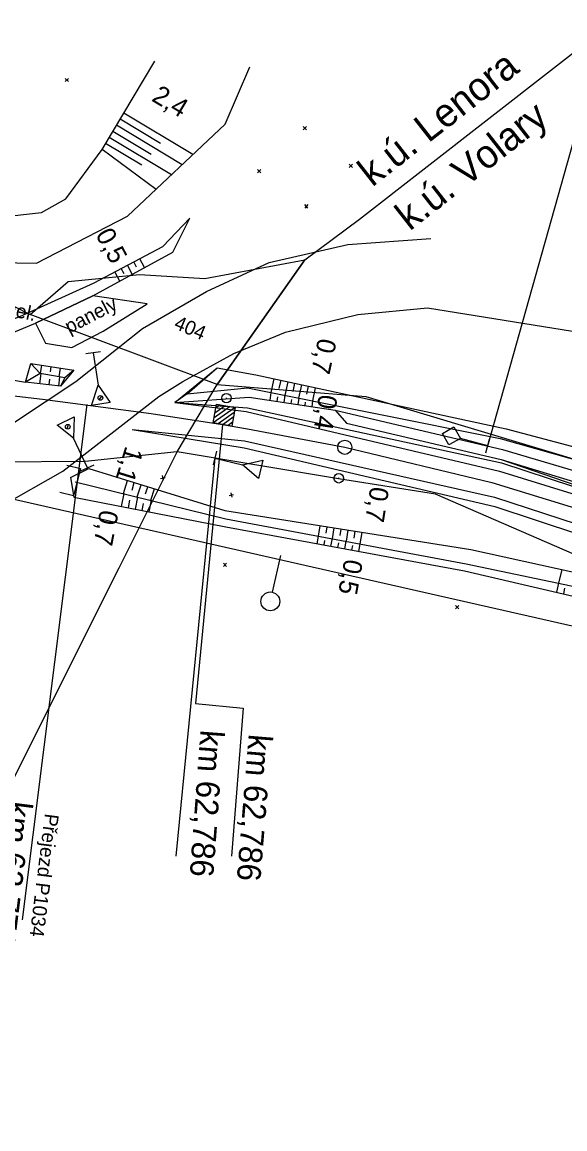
# Model space of a CAD drawing. Extents: x -804899 to -803847, y -1165742 to -1164942.
# Drawn here: x -804772 to -804714.3, y -1165193.1 to -1165075.5 of the extents above; entities that cross this region are included whole.
import ezdxf

# ---------------------------------------------------------------- set-up
doc = ezdxf.new("R2010")
doc.units = 0
for name, color, linetype in [('0381KM061-064P - Vrstva 1', 7, 'Continuous'), ('0381KM061-064P - Vrstva 16', 7, 'Continuous'), ('0381KM061-064P - Vrstva 27', 7, 'Continuous'), ('0381KM061-064P - Vrstva 3', 7, 'Continuous'), ('0381KM061-064P - Vrstva 36', 7, 'Continuous'), ('0381KM061-064P - Vrstva 4', 7, 'Continuous'), ('0381KM061-064P - Vrstva 43', 7, 'Continuous'), ('0381KM061-064P - Vrstva 48', 7, 'Continuous'), ('0381KM061-064P - Vrstva 49', 7, 'Continuous'), ('0381KM061-064P - Vrstva 51', 7, 'Continuous'), ('0381KM061-064P - Vrstva 55', 7, 'Continuous'), ('0381KM061-064P - Vrstva 57', 7, 'Continuous'), ('0381KM061-064P - Vrstva 7', 7, 'Continuous'), ('0381KM061-064P - Vrstva 8', 7, 'Continuous'), ('hran DP - hran DP', 7, 'Continuous'), ('vyt_sit - polygon', 7, 'Continuous')]:
    doc.layers.add(name, color=color, linetype=linetype)

msp = doc.modelspace()

# ---------------------------------------------------------------- linework, layer by layer
at = {"layer": '0381KM061-064P - Vrstva 1'}
for points in [[(-804783.45, -1165113.99), (-804769.78, -1165115.58), (-804758.24, -1165117.11), (-804750.67, -1165118.27), (-804748.02, -1165118.72)], [(-804748.02, -1165118.72), (-804737.69, -1165120.7), (-804722.06, -1165124.43), (-804702.11, -1165130.56), (-804682.19, -1165138.24), (-804666.44, -1165145.5)]]:
    msp.add_lwpolyline(points, dxfattribs=at)
at = {"layer": '0381KM061-064P - Vrstva 16'}
msp.add_lwpolyline([(-804770.54, -1165107.5), (-804769.47, -1165109.65), (-804766.68, -1165110.09), (-804763.36, -1165108.38), (-804758.69, -1165105.46), (-804764.44, -1165104.6), (-804770.54, -1165107.5)], dxfattribs=at)
at = {"layer": '0381KM061-064P - Vrstva 27'}
msp.add_line((-804750.31, -1165115.47), (-804750.21, -1165115.47), dxfattribs=at)
msp.add_circle((-804750.26, -1165115.47), 0.5, dxfattribs=at)
at = {"layer": '0381KM061-064P - Vrstva 3'}
for p, q in [((-804749.35, -1165116.47), (-804751.66, -1165118.1)), ((-804749.87, -1165116.38), (-804751.57, -1165117.58)), ((-804750.39, -1165116.29), (-804751.48, -1165117.06)), ((-804750.92, -1165116.2), (-804751.39, -1165116.53)), ((-804749.44, -1165116.99), (-804751.13, -1165118.19)), ((-804749.53, -1165117.51), (-804750.61, -1165118.28)), ((-804749.62, -1165118.04), (-804750.09, -1165118.37))]:
    msp.add_line(p, q, dxfattribs=at)
msp.add_lwpolyline([(-804749.68, -1165118.44), (-804751.66, -1165118.1), (-804751.32, -1165116.13), (-804749.35, -1165116.47)], close=True, dxfattribs=at)
msp.add_lwpolyline([(-804750.67, -1165118.27), (-804753.55, -1165147.9), (-804748.48, -1165148.39), (-804749.73, -1165164.12)], dxfattribs=at)
at = {"layer": '0381KM061-064P - Vrstva 36'}
for p, q in [((-804745.38, -1165136.08), (-804744.49, -1165132.18)), ((-804745.6, -1165137.06), (-804745.6, -1165137.06))]:
    msp.add_line(p, q, dxfattribs=at)
msp.add_circle((-804745.6, -1165137.06), 1, dxfattribs=at)
at = {"layer": '0381KM061-064P - Vrstva 4'}
for p, q in [((-804763.64, -1165110.55), (-804765.18, -1165110.78)), ((-804763.51, -1165115.25), (-804763.8, -1165115.65)), ((-804765.1, -1165116.15), (-804771.94, -1165170.89)), ((-804769.78, -1165115.58), (-804758.24, -1165117.11)), ((-804767.19, -1165118.74), (-804767.02, -1165118.28)), ((-804765.73, -1165123.21), (-804764.32, -1165122.55))]:
    msp.add_line(p, q, dxfattribs=at)
for points in [[(-804843.83, -1165105.73), (-804840.8, -1165106.06), (-804819.65, -1165108.38), (-804802.7, -1165110.3), (-804779.71, -1165112.39), (-804771.59, -1165113.78)], [(-804764.41, -1165110.67), (-804763.89, -1165114.11), (-804762.61, -1165115.94), (-804764.59, -1165116.25), (-804763.89, -1165114.11)], [(-804755.73, -1165115.93), (-804748.17, -1165116.91), (-804721.25, -1165123.25), (-804698.66, -1165130.22), (-804681.33, -1165136.99), (-804671.47, -1165141.65), (-804648.84, -1165153.36), (-804638.11, -1165160.03), (-804624.48, -1165168.7), (-804602.56, -1165183.07), (-804574.47, -1165201.72), (-804542.72, -1165222.84), (-804507.36, -1165246.55), (-804477.08, -1165266.82), (-804448.75, -1165285.88), (-804421.18, -1165304.15), (-804392.89, -1165323.09), (-804369.85, -1165338.37), (-804348.86, -1165352.04), (-804325.13, -1165367.98), (-804299.32, -1165385.27), (-804266.05, -1165407.31), (-804234.28, -1165428.6)], [(-804755.73, -1165115.93), (-804748.03, -1165116.49), (-804721.05, -1165122.36), (-804698.44, -1165129.77), (-804680.98, -1165136.5), (-804671.21, -1165140.89), (-804648.42, -1165152.46), (-804637.55, -1165159.43), (-804624.04, -1165168.29), (-804602.25, -1165182.38), (-804573.74, -1165201.2), (-804542.46, -1165222.56), (-804507.06, -1165246.03), (-804476.47, -1165266.24), (-804448.31, -1165285.08), (-804421.02, -1165303.1), (-804392.59, -1165322.59), (-804369.41, -1165337.65), (-804348.68, -1165351.59), (-804324.76, -1165367.42), (-804298.9, -1165384.42), (-804265.65, -1165406.5), (-804234.05, -1165428.04)], [(-804765.02, -1165122.88), (-804766.5, -1165119.73), (-804768.25, -1165118.34), (-804766.44, -1165117.48), (-804766.5, -1165119.73)], [(-804760.26, -1165118.8), (-804748.36, -1165120.01), (-804721.79, -1165126), (-804699.13, -1165133.38), (-804682.38, -1165139.58), (-804672.62, -1165144.09), (-804650.43, -1165155.7), (-804639.38, -1165162.29), (-804626.13, -1165170.89), (-804604.37, -1165185.52), (-804576.36, -1165204.15)], [(-804760.26, -1165118.8), (-804748.39, -1165120.75), (-804721.77, -1165126.98), (-804699.38, -1165134.38), (-804682.72, -1165140.57), (-804673.68, -1165144.67), (-804650.96, -1165156.64), (-804639.65, -1165163.02), (-804626.64, -1165171.43)]]:
    msp.add_lwpolyline(points, dxfattribs=at)
for centre in [(-804763.65, -1165115.45), (-804767.11, -1165118.51)]:
    msp.add_circle(centre, 0.248, dxfattribs=at)
at = {"layer": '0381KM061-064P - Vrstva 43'}
msp.add_lwpolyline([(-804767.23, -1165122.59), (-804765.77, -1165122.95), (-804766.49, -1165125.86), (-804767.94, -1165125.5)], dxfattribs=at)
at = {"layer": '0381KM061-064P - Vrstva 48'}
for p, q in [((-804757.25, -1165088.44), (-804761.55, -1165085.86)), ((-804753.82, -1165089.62), (-804761.16, -1165085.22)), ((-804758.24, -1165089.59), (-804762.32, -1165087.15)), ((-804754.95, -1165090.69), (-804761.93, -1165086.5)), ((-804756.09, -1165091.76), (-804762.7, -1165087.79)), ((-804757.74, -1165093.31), (-804763.47, -1165089.08)), ((-804759.23, -1165090.75), (-804763.09, -1165088.43)), ((-804759.81, -1165101.58), (-804760.11, -1165101.02)), ((-804758.95, -1165101.6), (-804759.45, -1165100.67)), ((-804761.58, -1165103.04), (-804762.1, -1165102.07)), ((-804761.13, -1165102.29), (-804761.43, -1165101.72)), ((-804760.27, -1165102.32), (-804760.77, -1165101.37)), ((-804769.98, -1165112.87), (-804770.1, -1165113.96)), ((-804770.01, -1165112.86), (-804769.87, -1165111.98)), ((-804768.96, -1165112.68), (-804768.88, -1165112.14)), ((-804768.04, -1165113.21), (-804767.89, -1165112.29)), ((-804769.04, -1165113.46), (-804769.11, -1165114.07)), ((-804768, -1165113.22), (-804768.11, -1165114.19)), ((-804745.51, -1165114.89), (-804745.19, -1165113.42)), ((-804744.65, -1165114.46), (-804744.46, -1165113.57)), ((-804744.04, -1165115.19), (-804743.72, -1165113.73)), ((-804743.18, -1165114.76), (-804742.99, -1165113.89)), ((-804742.57, -1165115.48), (-804742.26, -1165114.05)), ((-804741.71, -1165115.06), (-804741.53, -1165114.21)), ((-804745.53, -1165114.89), (-804745.65, -1165115.72)), ((-804744.84, -1165115.35), (-804744.91, -1165115.83)), ((-804744.06, -1165115.18), (-804744.17, -1165115.94)), ((-804741.1, -1165115.78), (-804740.79, -1165114.37)), ((-804743.36, -1165115.62), (-804743.43, -1165116.05)), ((-804742.58, -1165115.48), (-804742.69, -1165116.16)), ((-804741.89, -1165115.89), (-804741.95, -1165116.27)), ((-804741.11, -1165115.77), (-804741.2, -1165116.39)), ((-804761.18, -1165125.61), (-804760.76, -1165124.23)), ((-804760.29, -1165125.26), (-804760.05, -1165124.45)), ((-804759.73, -1165125.97), (-804759.33, -1165124.67)), ((-804761.17, -1165125.62), (-804761.44, -1165126.99)), ((-804758.85, -1165125.65), (-804758.62, -1165124.89)), ((-804758.28, -1165126.33), (-804757.91, -1165125.11)), ((-804760.55, -1165126.33), (-804760.71, -1165127.13)), ((-804759.72, -1165125.98), (-804759.97, -1165127.28)), ((-804759.09, -1165126.66), (-804759.24, -1165127.42)), ((-804758.26, -1165126.33), (-804758.5, -1165127.56)), ((-804740.47, -1165130.13), (-804740.3, -1165129.03)), ((-804739.66, -1165129.82), (-804739.55, -1165129.14)), ((-804738.99, -1165130.41), (-804738.81, -1165129.26)), ((-804738.18, -1165130.08), (-804738.07, -1165129.38)), ((-804740.52, -1165130.12), (-804740.67, -1165130.94)), ((-804739.84, -1165130.58), (-804739.93, -1165131.07)), ((-804739.05, -1165130.4), (-804739.2, -1165131.21)), ((-804737.52, -1165130.68), (-804737.33, -1165129.5)), ((-804736.71, -1165130.34), (-804736.59, -1165129.61)), ((-804736.05, -1165130.96), (-804735.85, -1165129.73)), ((-804738.37, -1165130.86), (-804738.46, -1165131.34)), ((-804737.57, -1165130.67), (-804737.72, -1165131.48)), ((-804736.89, -1165131.13), (-804736.98, -1165131.61)), ((-804736.1, -1165130.95), (-804736.24, -1165131.75)), ((-804714.95, -1165135.13), (-804714.62, -1165133.68)), ((-804714.99, -1165135.12), (-804715.21, -1165136.09)), ((-804714.35, -1165135.67), (-804714.48, -1165136.27))]:
    msp.add_line(p, q, dxfattribs=at)
at = {"layer": '0381KM061-064P - Vrstva 49'}
for p, q in [((-804767.04, -1165081.87), (-804767.4, -1165081.52)), ((-804767.04, -1165081.52), (-804767.4, -1165081.87)), ((-804741.77, -1165086.97), (-804742.13, -1165086.62)), ((-804741.77, -1165086.62), (-804742.13, -1165086.97)), ((-804736.88, -1165090.99), (-804737.23, -1165090.64)), ((-804736.88, -1165090.64), (-804737.23, -1165090.99)), ((-804746.62, -1165091.56), (-804746.97, -1165091.21)), ((-804746.62, -1165091.21), (-804746.97, -1165091.56)), ((-804741.6, -1165095.29), (-804741.95, -1165094.93)), ((-804741.6, -1165094.93), (-804741.95, -1165095.29)), ((-804770.54, -1165107.5), (-804764.44, -1165104.6)), ((-804767.44, -1165113.32), (-804770.04, -1165112.86)), ((-804757.27, -1165124.01), (-804756.78, -1165123.9)), ((-804757.08, -1165123.71), (-804756.97, -1165124.2)), ((-804749.98, -1165125.83), (-804749.5, -1165125.71)), ((-804749.8, -1165125.53), (-804749.68, -1165126.01)), ((-804750.24, -1165133.35), (-804750.59, -1165133)), ((-804750.24, -1165133), (-804750.59, -1165133.35)), ((-804725.58, -1165137.85), (-804725.93, -1165137.5)), ((-804725.58, -1165137.5), (-804725.93, -1165137.85))]:
    msp.add_line(p, q, dxfattribs=at)
for points in [[(-804769.92, -1165095.77), (-804767.33, -1165094.3), (-804763.47, -1165089.08), (-804757.86, -1165079.71)], [(-804782.93, -1165100.95), (-804770.45, -1165101.13), (-804760.77, -1165096.17), (-804750.38, -1165086.38), (-804747.77, -1165080.29)], [(-804834.14, -1165089.82), (-804812.85, -1165092.56), (-804796.39, -1165094.52), (-804782.73, -1165096.03), (-804774.67, -1165096.28), (-804769.92, -1165095.77)], [(-804778.12, -1165109.25), (-804771.87, -1165106.67), (-804764.3, -1165103.24), (-804757.01, -1165099.37), (-804754.14, -1165096.35)], [(-804764.44, -1165104.6), (-804755.94, -1165099.96), (-804754.14, -1165096.35)], [(-804778.59, -1165110.84), (-804770.54, -1165107.5)], [(-804771.02, -1165111.8), (-804770.04, -1165112.86), (-804771.59, -1165113.78)], [(-804766.48, -1165112.51), (-804767.44, -1165113.32), (-804767.89, -1165114.22)], [(-804755.73, -1165115.93), (-804751.24, -1165112.25), (-804747.15, -1165112.99), (-804720.56, -1165118.75), (-804697.46, -1165124.86)], [(-804754.42, -1165115.02), (-804751.24, -1165112.25)], [(-804754.42, -1165115.02), (-804755.73, -1165115.93)], [(-804754.42, -1165115.02), (-804748.04, -1165114.39), (-804721.19, -1165119.75), (-804697.28, -1165126.54)], [(-804755.73, -1165115.93), (-804747.85, -1165115.39), (-804738.73, -1165116.75), (-804720.93, -1165120.92), (-804697.63, -1165127.82)], [(-804738.73, -1165116.75), (-804737.5, -1165118.13), (-804721.08, -1165121.98), (-804698.17, -1165128.96), (-804680.73, -1165135.83), (-804670.75, -1165140.27), (-804648.42, -1165152.46)], [(-804721.08, -1165121.98), (-804698.44, -1165129.77), (-804680.98, -1165136.5), (-804671.21, -1165140.89), (-804648.42, -1165152.46)], [(-804766.83, -1165123.91), (-804764.89, -1165122.96), (-804750.44, -1165127.42), (-804724.29, -1165131.56), (-804700.35, -1165136.81), (-804683.35, -1165141.96), (-804673.48, -1165145.6), (-804651.73, -1165158.22)], [(-804766.83, -1165123.91), (-804766.46, -1165126.01)], [(-804766.32, -1165124.35), (-804750.31, -1165128.3), (-804724.8, -1165133.06), (-804699.44, -1165138.4), (-804683.58, -1165142.5), (-804673.52, -1165146.32), (-804651.73, -1165158.22)], [(-804766.46, -1165126.01), (-804750.34, -1165129.15), (-804724.99, -1165133.83)], [(-804724.99, -1165133.83), (-804700.39, -1165139.54), (-804683.82, -1165143.08), (-804673.79, -1165147.18), (-804651.73, -1165158.22)]]:
    msp.add_lwpolyline(points, dxfattribs=at)
msp.add_lwpolyline([(-804771.59, -1165113.78), (-804771.02, -1165111.8), (-804766.48, -1165112.51), (-804767.89, -1165114.22)], close=True, dxfattribs=at)
at = {"layer": '0381KM061-064P - Vrstva 51'}
for points in [[(-804799.4, -1165124.13), (-804788.79, -1165123.56), (-804781.18, -1165122.08), (-804777.38, -1165120.68), (-804772.77, -1165118.03), (-804766.25, -1165113.72), (-804759.19, -1165108.08), (-804752.39, -1165104.15), (-804745.74, -1165101.09), (-804737.37, -1165099.16), (-804728.56, -1165098.53)], [(-804786.51, -1165130.38), (-804780.05, -1165129.08), (-804774.13, -1165126.91), (-804767.62, -1165123.23), (-804757.45, -1165115.32), (-804754.9, -1165113.7), (-804749.49, -1165110.74), (-804743.99, -1165108.46), (-804736.29, -1165106.6), (-804728.9, -1165105.9)], [(-804728.9, -1165105.9), (-804711.54, -1165108.67), (-804704.35, -1165111.8), (-804683.69, -1165124.09), (-804676.95, -1165128.43), (-804667.36, -1165134.41), (-804645.71, -1165148.3), (-804634.7, -1165155.23), (-804621.63, -1165163.62), (-804599.19, -1165178.23), (-804569.67, -1165197.16), (-804538.42, -1165216.77), (-804503.41, -1165238.94), (-804472.82, -1165258.55), (-804444.57, -1165276.4), (-804415.82, -1165294.73), (-804384.7, -1165314.57), (-804342.59, -1165341.72), (-804321.8, -1165355.02), (-804291.77, -1165374.22), (-804262.45, -1165392.96)]]:
    msp.add_lwpolyline(points, dxfattribs=at)
at = {"layer": '0381KM061-064P - Vrstva 55'}
msp.add_lwpolyline([(-804834.02, -1165173.21), (-804777.95, -1165165.95), (-804761.65, -1165133.49), (-804755.48, -1165121.19), (-804751.26, -1165114.04), (-804741.92, -1165100.8), (-804736.13, -1165096.49), (-804701.79, -1165069.72), (-804628.3, -1165012.44)], dxfattribs=at)
msp.add_lwpolyline([(-804771.09, -1165106.6), (-804767.08, -1165103.1), (-804759.5, -1165102.35), (-804752.56, -1165102.78), (-804741.92, -1165100.8), (-804751.26, -1165114.04)], close=True, dxfattribs=at)
at = {"layer": '0381KM061-064P - Vrstva 7'}
msp.add_line((-804738.29, -1165124), (-804738.39, -1165123.98), dxfattribs=at)
for centre, radius in [((-804737.69, -1165120.7), 0.75), ((-804738.34, -1165123.99), 0.5)]:
    msp.add_circle(centre, radius, dxfattribs=at)
at = {"layer": '0381KM061-064P - Vrstva 8'}
for p, q in [((-804722.5, -1165120.54), (-804702.47, -1165049.27)), ((-804722.7, -1165121.27), (-804722.31, -1165119.82)), ((-804751.3, -1165121.11), (-804751.66, -1165122.57)), ((-804751.48, -1165121.84), (-804755.65, -1165164.12)), ((-804746.86, -1165124), (-804748.56, -1165122.55))]:
    msp.add_line(p, q, dxfattribs=at)
for points in [[(-804722.5, -1165120.54), (-804725.4, -1165119.75), (-804726.63, -1165120.45), (-804727.33, -1165119.22), (-804726.1, -1165118.52), (-804725.4, -1165119.75)], [(-804751.48, -1165121.84), (-804748.56, -1165122.55), (-804746.38, -1165122.05), (-804746.86, -1165124), (-804748.56, -1165122.55)]]:
    msp.add_lwpolyline(points, dxfattribs=at)
at = {"layer": 'hran DP - hran DP'}
for p, q in [((-804752.56, -1165102.78), (-804741.92, -1165100.8)), ((-804741.92, -1165100.8), (-804751.26, -1165114.04)), ((-804767.08, -1165103.1), (-804759.5, -1165102.35)), ((-804759.5, -1165102.35), (-804752.56, -1165102.78)), ((-804777.08, -1165103.56), (-804771.09, -1165106.6)), ((-804771.09, -1165106.6), (-804767.08, -1165103.1)), ((-804751.26, -1165114.04), (-804735.44, -1165115.31)), ((-804735.44, -1165115.31), (-804706.98, -1165123.89)), ((-804755.48, -1165121.19), (-804765.27, -1165122.22)), ((-804738.35, -1165124.03), (-804755.48, -1165121.19)), ((-804765.27, -1165122.22), (-804781.51, -1165122.32)), ((-804728.07, -1165125.68), (-804738.35, -1165124.03)), ((-804647.39, -1165160.7), (-804728.07, -1165125.68))]:
    msp.add_line(p, q, dxfattribs=at)
at = {"layer": 'vyt_sit - polygon'}
msp.add_line((-804641.93, -1165155.93), (-804836.52, -1165111.83), dxfattribs=at)

# ---------------------------------------------------------------- texts
at = {"layer": '0381KM061-064P - Vrstva 16'}
for s, rotation, p in [('panel.', 348.0707, (-804776, -1165106.18)), ('panely', 27.2719, (-804766.95, -1165108.66))]:
    msp.add_text(s, height=1.5, rotation=rotation, dxfattribs=at).set_placement(p)
at = {"layer": '0381KM061-064P - Vrstva 3'}
msp.add_text('km 62,786', height=2.5, rotation=265.3169, dxfattribs=at).set_placement((-804747.89, -1165151.1))
at = {"layer": '0381KM061-064P - Vrstva 4'}
for s, height, p in [('km 62,771', 2.5, (-804773.35, -1165158.16)), ('Přejezd P1034', 1.5, (-804769.54, -1165159.54))]:
    msp.add_text(s, height=height, rotation=262.8793, dxfattribs=at).set_placement(p)
at = {"layer": '0381KM061-064P - Vrstva 48'}
for s, rotation, p in [('2,4', 329.0731, (-804758.31, -1165083.85)), ('0,5', 297.9687, (-804764.21, -1165098.09)), ('0,7', 257.7952, (-804740.5, -1165109.01)), ('0,4', 261.5009, (-804740.43, -1165115.01)), ('1,1', 252.8402, (-804760.96, -1165120.49)), ('0,7', 261.0049, (-804734.96, -1165124.79)), ('0,7', 258.9794, (-804763.67, -1165127.25)), ('0,5', 259.5558, (-804737.72, -1165132.48))]:
    msp.add_text(s, height=2, rotation=rotation, dxfattribs=at).set_placement(p)
at = {"layer": '0381KM061-064P - Vrstva 55'}
for s, p in [('k.ú. Lenora', (-804734.78, -1165093.12)), ('k.ú. Volary', (-804730.8, -1165097.79))]:
    msp.add_text(s, height=3, rotation=38.104, dxfattribs=at).set_placement(p)
at = {"layer": '0381KM061-064P - Vrstva 57'}
msp.add_text('404', height=1.5, rotation=336.9346, dxfattribs=at).set_placement((-804755.93, -1165108.04))
at = {"layer": '0381KM061-064P - Vrstva 8'}
msp.add_text('km 62,786', height=2.5, rotation=265.7808, dxfattribs=at).set_placement((-804753.01, -1165150.66))

doc.saveas('drawing.dxf')
